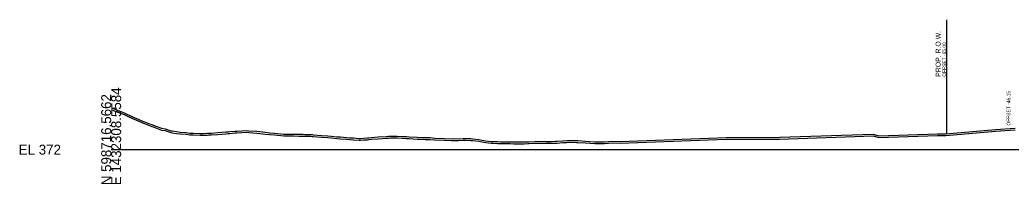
# Model space of a CAD drawing. Extents: x -26 to 2203, y -10 to 12201.
# Drawn here: x -25.7 to 253.1, y 8990.3 to 9036.5 of the extents above; entities that cross this region are included whole.
import ezdxf

# ---------------------------------------------------------------- set-up
doc = ezdxf.new("R2010")
doc.units = 0
for name, color, linetype in [('DESIGN - ROW - Right-of-Way and Easement Labels', 7, 'Continuous'), ('DESIGN - ROW - Right-of-Way Linework', 7, 'Continuous'), ('DESIGN - SHEET - Light Grid', 7, 'Continuous'), ('DESIGN - TYPICAL - Slope Tie Text', 7, 'Continuous'), ('SURVEY - GROUND - Bottom of Topsoil Layer', 7, 'Continuous'), ('SURVEY - GROUND - Top of Ground', 7, 'Continuous')]:
    doc.layers.add(name, color=color, linetype=linetype)

msp = doc.modelspace()

# ---------------------------------------------------------------- linework, layer by layer
at = {"layer": 'DESIGN - ROW - Right-of-Way Linework'}
msp.add_line((235, 9004.48), (235, 9036.48), dxfattribs=at)
at = {"layer": 'DESIGN - SHEET - Light Grid'}
msp.add_line((0, 9000), (300, 9000), dxfattribs=at)
at = {"layer": 'SURVEY - GROUND - Bottom of Topsoil Layer'}
for p, q in [((0, 9011.28), (0.86, 9010.95)), ((0.86, 9010.95), (3.64, 9009.87)), ((3.64, 9009.87), (6.16, 9008.65)), ((6.16, 9008.65), (7.37, 9008.19)), ((7.37, 9008.19), (8.82, 9007.5)), ((8.82, 9007.5), (9.33, 9007.34)), ((9.33, 9007.34), (10.81, 9006.76)), ((10.81, 9006.76), (11.47, 9006.53)), ((11.47, 9006.53), (11.82, 9006.38)), ((11.82, 9006.38), (14.12, 9005.52)), ((14.12, 9005.52), (15.22, 9005.38)), ((15.22, 9005.38), (16.77, 9004.79)), ((16.77, 9004.79), (17.18, 9004.77)), ((35.32, 9004.73), (36.78, 9004.79)), ((36.78, 9004.79), (37.97, 9004.87)), ((37.97, 9004.87), (38.74, 9004.82)), ((38.74, 9004.82), (40.92, 9004.67)), ((234.74, 9003.95), (248.68, 9005.16)), ((248.68, 9005.16), (254.23, 9005.53)), ((17.18, 9004.77), (18.34, 9004.58)), ((18.34, 9004.58), (19.42, 9004.43)), ((19.42, 9004.43), (21.1, 9004.32)), ((21.1, 9004.32), (22.07, 9004.17)), ((22.07, 9004.17), (23.06, 9004.14)), ((23.06, 9004.14), (25.02, 9004.07)), ((25.02, 9004.07), (25.86, 9004.08)), ((25.86, 9004.08), (26.98, 9004.11)), ((26.98, 9004.11), (27.37, 9004.12)), ((27.37, 9004.12), (28.19, 9004.18)), ((28.19, 9004.18), (30.02, 9004.3)), ((30.02, 9004.3), (32.28, 9004.48)), ((32.28, 9004.48), (32.86, 9004.53)), ((32.86, 9004.53), (33.39, 9004.57)), ((33.39, 9004.57), (34.82, 9004.69)), ((34.82, 9004.69), (35.32, 9004.73)), ((40.92, 9004.67), (42.66, 9004.48)), ((42.66, 9004.48), (43.27, 9004.4)), ((43.27, 9004.4), (44.55, 9004.26)), ((44.55, 9004.26), (45.92, 9004.13)), ((45.92, 9004.13), (48.58, 9003.87)), ((48.58, 9003.87), (50.5, 9003.89)), ((50.5, 9003.89), (51.23, 9003.86)), ((51.23, 9003.86), (52.74, 9003.82)), ((52.74, 9003.82), (53.88, 9003.82)), ((53.88, 9003.82), (54.42, 9003.8)), ((54.42, 9003.8), (55.97, 9003.75)), ((55.97, 9003.75), (56.53, 9003.73)), ((56.53, 9003.73), (56.83, 9003.7)), ((56.83, 9003.7), (59.18, 9003.52)), ((59.18, 9003.52), (60.92, 9003.37)), ((60.92, 9003.37), (61.83, 9003.31)), ((61.83, 9003.31), (63.5, 9003.15)), ((63.5, 9003.15), (64.48, 9003.08)), ((64.48, 9003.08), (66.18, 9002.93)), ((66.18, 9002.93), (67.13, 9002.86)), ((67.13, 9002.86), (68.14, 9002.79)), ((68.14, 9002.79), (69.78, 9002.65)), ((69.78, 9002.65), (70.1, 9002.64)), ((70.1, 9002.64), (71.02, 9002.72)), ((71.02, 9002.72), (72.06, 9002.8)), ((72.06, 9002.8), (72.43, 9002.83)), ((72.43, 9002.83), (73.2, 9002.93)), ((73.2, 9002.93), (75.08, 9003.07)), ((75.08, 9003.07), (77.29, 9003.23)), ((77.29, 9003.23), (77.95, 9003.26)), ((77.95, 9003.26), (78.55, 9003.29)), ((78.55, 9003.29), (79.91, 9003.31)), ((79.91, 9003.31), (80.38, 9003.32)), ((80.38, 9003.32), (81.87, 9003.24)), ((81.87, 9003.24), (83.03, 9003.16)), ((83.03, 9003.16), (83.83, 9003.09)), ((83.83, 9003.09), (86.08, 9002.97)), ((86.08, 9002.97), (87.75, 9002.91)), ((87.75, 9002.91), (88.33, 9002.88)), ((88.33, 9002.88), (89.71, 9002.88)), ((89.71, 9002.88), (90.99, 9002.77)), ((90.99, 9002.77), (93.64, 9002.65)), ((93.64, 9002.65), (95.59, 9002.55)), ((95.59, 9002.55), (96.29, 9002.59)), ((96.29, 9002.59), (97.55, 9002.55)), ((97.55, 9002.55), (98.94, 9002.66)), ((98.94, 9002.66), (99.51, 9002.64)), ((99.51, 9002.64), (101.13, 9002.61)), ((101.13, 9002.61), (101.59, 9002.58)), ((101.59, 9002.58), (103.43, 9002.37)), ((103.43, 9002.37), (104.24, 9002.2)), ((104.24, 9002.2), (105.39, 9002.02)), ((105.39, 9002.02), (106.89, 9001.82)), ((126.95, 9001.97), (128.09, 9002.04)), ((128.09, 9002.04), (128.91, 9002.08)), ((128.91, 9002.08), (130.87, 9002.05)), ((130.87, 9002.05), (131.24, 9002.03)), ((131.24, 9002.03), (133.4, 9001.89)), ((143.14, 9001.81), (172.99, 9002.95)), ((172.99, 9002.95), (187.93, 9002.99)), ((187.93, 9002.99), (214.31, 9003.87)), ((214.31, 9003.87), (215.91, 9003.39)), ((215.91, 9003.39), (232.35, 9003.94)), ((232.35, 9003.94), (234.74, 9003.95)), ((106.89, 9001.82), (107.35, 9001.8)), ((107.35, 9001.8), (108.66, 9001.77)), ((108.66, 9001.77), (109.54, 9001.74)), ((109.54, 9001.74), (111.27, 9001.71)), ((111.27, 9001.71), (112.19, 9001.7)), ((112.19, 9001.7), (113.23, 9001.68)), ((113.23, 9001.68), (114.84, 9001.67)), ((114.84, 9001.67), (116.18, 9001.68)), ((116.18, 9001.68), (117.15, 9001.71)), ((117.15, 9001.71), (117.49, 9001.71)), ((117.49, 9001.71), (119.11, 9001.82)), ((119.11, 9001.82), (120.14, 9001.84)), ((120.14, 9001.84), (122.3, 9001.79)), ((122.3, 9001.79), (123.03, 9001.81)), ((123.03, 9001.81), (123.71, 9001.81)), ((123.71, 9001.81), (124.99, 9001.85)), ((124.99, 9001.85), (125.44, 9001.84)), ((125.44, 9001.84), (126.95, 9001.97)), ((133.4, 9001.89), (134.57, 9001.82)), ((134.57, 9001.82), (136.05, 9001.73)), ((136.05, 9001.73), (138.76, 9001.74)), ((138.76, 9001.74), (140.96, 9001.89)), ((140.96, 9001.89), (143.14, 9001.81))]:
    msp.add_line(p, q, dxfattribs=at)
at = {"layer": 'SURVEY - GROUND - Top of Ground'}
for p, q in [((0, 9011.78), (0.86, 9011.45)), ((0.86, 9011.45), (3.64, 9010.37)), ((3.64, 9010.37), (6.16, 9009.15)), ((6.16, 9009.15), (7.37, 9008.69)), ((7.37, 9008.69), (8.82, 9008)), ((8.82, 9008), (9.33, 9007.84)), ((9.33, 9007.84), (10.81, 9007.26)), ((10.81, 9007.26), (11.47, 9007.03)), ((11.47, 9007.03), (11.82, 9006.88)), ((11.82, 9006.88), (14.12, 9006.02)), ((14.12, 9006.02), (15.22, 9005.88)), ((15.22, 9005.88), (16.77, 9005.29)), ((16.77, 9005.29), (17.18, 9005.27)), ((17.18, 9005.27), (18.34, 9005.08)), ((18.34, 9005.08), (19.42, 9004.93)), ((19.42, 9004.93), (21.1, 9004.82)), ((21.1, 9004.82), (22.07, 9004.67)), ((28.19, 9004.68), (30.02, 9004.8)), ((30.02, 9004.8), (32.28, 9004.98)), ((32.28, 9004.98), (32.86, 9005.03)), ((32.86, 9005.03), (33.39, 9005.07)), ((33.39, 9005.07), (34.82, 9005.19)), ((34.82, 9005.19), (35.32, 9005.23)), ((35.32, 9005.23), (36.78, 9005.29)), ((36.78, 9005.29), (37.97, 9005.37)), ((37.97, 9005.37), (38.74, 9005.32)), ((38.74, 9005.32), (40.92, 9005.17)), ((40.92, 9005.17), (42.66, 9004.98)), ((42.66, 9004.98), (43.27, 9004.9)), ((43.27, 9004.9), (44.55, 9004.76)), ((234.74, 9004.45), (248.68, 9005.66)), ((248.68, 9005.66), (254.23, 9006.03)), ((22.07, 9004.67), (23.06, 9004.64)), ((23.06, 9004.64), (25.02, 9004.57)), ((25.02, 9004.57), (25.86, 9004.58)), ((25.86, 9004.58), (26.98, 9004.61)), ((26.98, 9004.61), (27.37, 9004.62)), ((27.37, 9004.62), (28.19, 9004.68)), ((44.55, 9004.76), (45.92, 9004.63)), ((45.92, 9004.63), (48.58, 9004.37)), ((48.58, 9004.37), (50.5, 9004.39)), ((50.5, 9004.39), (51.23, 9004.36)), ((51.23, 9004.36), (52.74, 9004.32)), ((52.74, 9004.32), (53.88, 9004.32)), ((53.88, 9004.32), (54.42, 9004.3)), ((54.42, 9004.3), (55.97, 9004.25)), ((55.97, 9004.25), (56.53, 9004.23)), ((56.53, 9004.23), (56.83, 9004.2)), ((56.83, 9004.2), (59.18, 9004.02)), ((59.18, 9004.02), (60.92, 9003.87)), ((60.92, 9003.87), (61.83, 9003.81)), ((61.83, 9003.81), (63.5, 9003.65)), ((63.5, 9003.65), (64.48, 9003.58)), ((64.48, 9003.58), (66.18, 9003.43)), ((66.18, 9003.43), (67.13, 9003.36)), ((67.13, 9003.36), (68.14, 9003.29)), ((68.14, 9003.29), (69.78, 9003.15)), ((69.78, 9003.15), (70.1, 9003.14)), ((70.1, 9003.14), (71.02, 9003.22)), ((71.02, 9003.22), (72.06, 9003.3)), ((72.06, 9003.3), (72.43, 9003.33)), ((72.43, 9003.33), (73.2, 9003.43)), ((73.2, 9003.43), (75.08, 9003.57)), ((75.08, 9003.57), (77.29, 9003.73)), ((77.29, 9003.73), (77.95, 9003.76)), ((77.95, 9003.76), (78.55, 9003.79)), ((78.55, 9003.79), (79.91, 9003.81)), ((79.91, 9003.81), (80.38, 9003.82)), ((80.38, 9003.82), (81.87, 9003.74)), ((81.87, 9003.74), (83.03, 9003.66)), ((83.03, 9003.66), (83.83, 9003.59)), ((83.83, 9003.59), (86.08, 9003.47)), ((86.08, 9003.47), (87.75, 9003.41)), ((87.75, 9003.41), (88.33, 9003.38)), ((88.33, 9003.38), (89.71, 9003.38)), ((89.71, 9003.38), (90.99, 9003.27)), ((90.99, 9003.27), (93.64, 9003.15)), ((93.64, 9003.15), (95.59, 9003.05)), ((95.59, 9003.05), (96.29, 9003.09)), ((96.29, 9003.09), (97.55, 9003.05)), ((97.55, 9003.05), (98.94, 9003.16)), ((98.94, 9003.16), (99.51, 9003.14)), ((99.51, 9003.14), (101.13, 9003.11)), ((101.13, 9003.11), (101.59, 9003.08)), ((101.59, 9003.08), (103.43, 9002.87)), ((103.43, 9002.87), (104.24, 9002.7)), ((104.24, 9002.7), (105.39, 9002.52)), ((105.39, 9002.52), (106.89, 9002.32)), ((106.89, 9002.32), (107.35, 9002.3)), ((107.35, 9002.3), (108.66, 9002.27)), ((108.66, 9002.27), (109.54, 9002.24)), ((109.54, 9002.24), (111.27, 9002.21)), ((111.27, 9002.21), (112.19, 9002.2)), ((112.19, 9002.2), (113.23, 9002.18)), ((113.23, 9002.18), (114.84, 9002.17)), ((114.84, 9002.17), (116.18, 9002.18)), ((116.18, 9002.18), (117.15, 9002.21)), ((117.15, 9002.21), (117.49, 9002.21)), ((117.49, 9002.21), (119.11, 9002.32)), ((119.11, 9002.32), (120.14, 9002.34)), ((120.14, 9002.34), (122.3, 9002.29)), ((122.3, 9002.29), (123.03, 9002.31)), ((123.03, 9002.31), (123.71, 9002.31)), ((123.71, 9002.31), (124.99, 9002.35)), ((124.99, 9002.35), (125.44, 9002.34)), ((125.44, 9002.34), (126.95, 9002.47)), ((126.95, 9002.47), (128.09, 9002.54)), ((128.09, 9002.54), (128.91, 9002.58)), ((128.91, 9002.58), (130.87, 9002.55)), ((130.87, 9002.55), (131.24, 9002.53)), ((131.24, 9002.53), (133.4, 9002.39)), ((133.4, 9002.39), (134.57, 9002.32)), ((134.57, 9002.32), (136.05, 9002.23)), ((136.05, 9002.23), (138.76, 9002.24)), ((138.76, 9002.24), (140.96, 9002.39)), ((140.96, 9002.39), (143.14, 9002.31)), ((143.14, 9002.31), (172.99, 9003.45)), ((172.99, 9003.45), (187.93, 9003.49)), ((187.93, 9003.49), (214.31, 9004.37)), ((214.31, 9004.37), (215.91, 9003.89)), ((215.91, 9003.89), (232.35, 9004.44)), ((232.35, 9004.44), (234.74, 9004.45))]:
    msp.add_line(p, q, dxfattribs=at)

# ---------------------------------------------------------------- texts
at = {"layer": 'DESIGN - ROW - Right-of-Way and Easement Labels'}
for s, height, p in [('PROP. R.O.W.', 1.4, (233.25, 9020.48)), ('OFFSET -65.00', 1, (234.75, 9020.48))]:
    msp.add_text(s, height=height, rotation=90, dxfattribs=at).set_placement(p)
at = {"layer": 'DESIGN - SHEET - Light Grid'}
for s, p in [('E 1432308.5584', (2.8, 8990)), ('N 598716.5662', (0, 8990))]:
    msp.add_text(s, height=2.8, rotation=90, dxfattribs=at).set_placement(p)
msp.add_text('EL 372', height=2.8, dxfattribs=at).set_placement((-26, 8998.6))
at = {"layer": 'DESIGN - TYPICAL - Slope Tie Text'}
msp.add_text('OFFSET -46.15', height=1, rotation=90, dxfattribs=at).set_placement((252.85, 9006.76))

doc.saveas('drawing.dxf')
